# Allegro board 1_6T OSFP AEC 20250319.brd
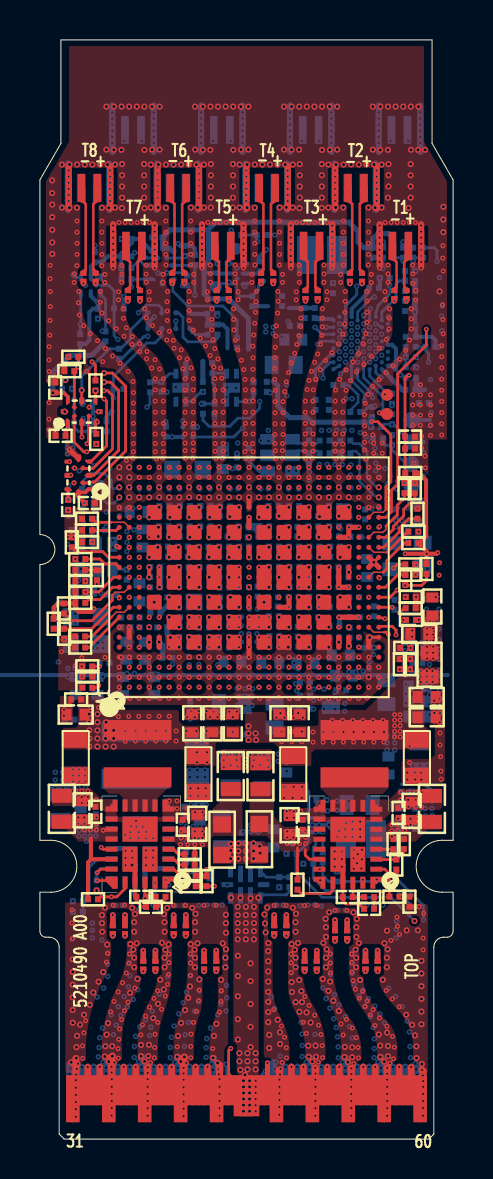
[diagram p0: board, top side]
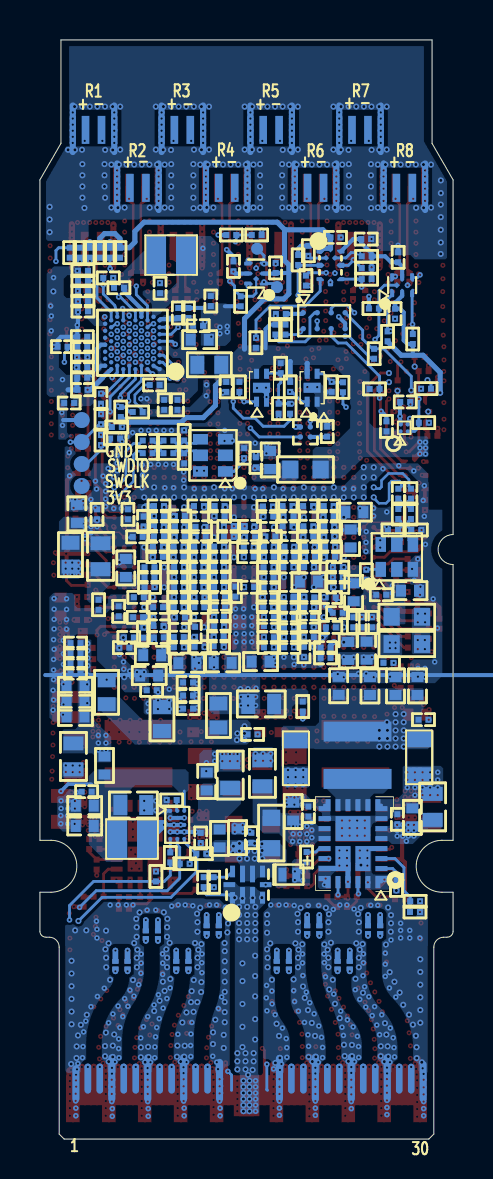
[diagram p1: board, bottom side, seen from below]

Outline 20.7 x 55 mm; copper layers: TOP, L2_GND, L3_GND, L4_SIG1, L5_GND, L6_PWR1, L7_PWR2, L8_GND, L9_SIG2, L10_GND, L11_GND, BOTTOM. Coordinates in mm from the lower left corner of the outline.
Outline path: 0,48 0,30.25 arc(0.75,29.5) 0,28.75 0,14.95 0.56,14.95 arc(1.86,13.65) 0.56,12.35 0,12.35 0,10.4 arc(0.09,10.19) 0.3,10.1 0.46,10.1 arc(0.82,9.95) 0.96,9.6 0.96,0.25 1.21,0 19.48,0 19.74,0.25 19.74,9.6 arc(19.88,9.95) 20.23,10.1 20.4,10.1 arc(20.61,10.19) 20.7,10.4 20.7,12.35 20.14,12.35 arc(18.84,13.65) 20.14,14.95 20.7,14.95 20.7,48 19.65,49.83 19.65,55 1.05,55 1.05,49.83 0,48

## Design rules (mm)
constraint set DEFAULT: min track width 0.14, pair gap 0.264
net group AVDDTXDRV_0P94: nets AVDDTXDRV_0P94 VDD_0P94
net group COMP1: nets COMP1 N17728804
net group DP1: nets LRXN1 LRXP1
net group DP2: nets LRXN2 LRXP2
net group DP3: nets LRXN3 LRXP3
net group DP4: nets LRXN4 LRXP4
net group DP5: nets LRXN5 LRXP5
net group DP6: nets LRXN6 LRXP6
net group DP7: nets LRXN7 LRXP7
net group DP8: nets LRXN8 LRXP8
net group DSP_PGOOD_M: nets DSP_PGOOD_M N17324668
net group EN1: nets EN1 N17689668
net group HRXN1: nets HRXN1 TXN1
net group HRXN2: nets HRXN2 TXN2
net group HRXN3: nets HRXN3 TXN3
net group HRXN4: nets HRXN4 TXN4
net group HRXN5: nets HRXN5 TXN5
net group HRXN6: nets HRXN6 TXN6
net group HRXN7: nets HRXN7 TXN7
net group HRXN8: nets HRXN8 TXN8
net group HRXP1: nets HRXP1 TXP1
net group HRXP2: nets HRXP2 TXP2
net group HRXP3: nets HRXP3 TXP3
net group HRXP4: nets HRXP4 TXP4
net group HRXP5: nets HRXP5 TXP5
net group HRXP6: nets HRXP6 TXP6
net group HRXP7: nets HRXP7 TXP7
net group HRXP8: nets HRXP8 TXP8
net group HTXN1: nets HTXN1 RXN1
net group HTXN2: nets HTXN2 RXN2
net group HTXN3: nets HTXN3 RXN3
net group HTXN4: nets HTXN4 RXN4
net group HTXN5: nets HTXN5 RXN5
net group HTXN6: nets HTXN6 RXN6
net group HTXN7: nets HTXN7 RXN7
net group HTXN8: nets HTXN8 RXN8
net group HTXP1: nets HTXP1 RXP1
net group HTXP2: nets HTXP2 RXP2
net group HTXP3: nets HTXP3 RXP3
net group HTXP4: nets HTXP4 RXP4
net group HTXP5: nets HTXP5 RXP5
net group HTXP6: nets HTXP6 RXP6
net group HTXP7: nets HTXP7 RXP7
net group HTXP8: nets HTXP8 RXP8
net group LTXN1: nets LTX_N1 LTXN1
net group LTXN2: nets LTX_N2 LTXN2
net group LTXN3: nets LTX_N3 LTXN3
net group LTXN4: nets LTX_N4 LTXN4
net group LTXN5: nets LTX_N5 LTXN5
net group LTXN6: nets LTX_N6 LTXN6
net group LTXN7: nets LTX_N7 LTXN7
net group LTXN8: nets LTX_N8 LTXN8
net group LTXP1: nets LTX_P1 LTXP1
net group LTXP2: nets LTX_P2 LTXP2
net group LTXP3: nets LTX_P3 LTXP3
net group LTXP4: nets LTX_P4 LTXP4
net group LTXP5: nets LTX_P5 LTXP5
net group LTXP6: nets LTX_P6 LTXP6
net group LTXP7: nets LTX_P7 LTXP7
net group LTXP8: nets LTX_P8 LTXP8
net group M_RSTN: nets M_RSTN NRST
net group MCU_SPI_CLK: nets MCU_SPI_CLK N17609315
net group MCU_SPI_CSB: nets MCU_SPI_CSB N17609312
net group MCU_SPI_MISO: nets MCU_SPI_MISO N17609318
net group MCU_SPI_MOSI: nets MCU_SPI_MOSI N17609321
net group N17421630: nets N16845549 N17421630
net group N17421668: nets N16845553 N17421668
net group N17495716: nets N17495710 N17495716
net group N17495757: nets N17495751 N17495757
net group N17738812: nets N17341552 N17738812
net group REFOUT0_CLK: nets DSP_REFCLK0_N DSP_REFCLK0_P
net group VCAP: nets VCAP VLXSMPS
net group 3V3_IN_DDM: nets 3V3_IN_DDM N17477873 VCC_OSFP
net group INT/RSTN: nets INT/RSTN M_INT OSFP_SCL SWDIO
net group LPWN/PRSN: nets LPWN/PRSN OSFP_SDA SWCLK
net group MISO_SLV_18: nets MISO_SLV_18 N17630589 N17630592
net group PHY_SELF_INIT_18: nets N17636718 N17636870 PHY_SELF_INIT_18
net group SE_50: nets EEPROM_MISO EEPROM_MOSI EEPROM_SCK
net group VDD_1P2: nets N17342760
net group VDD_3P3: nets VDD_3P3 VDD_3P3_ESD0 VDD_3P3_ESD1

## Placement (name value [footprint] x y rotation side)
C40  1uF  [0201C]  18.54 35.15 180 top
C42  0.1uF  [0201C]  14.48 36.74 90 bottom
C43  0.1uF  [0201C]  17.28 43.09 0 bottom
C45  0.1uF  [0201C]  8.63 41.29 0 bottom
C48  0.1uF  [0201C]  3.6 27.24 0 bottom
C49  22uF  [0402C]  2.16 27.44 180 bottom
C50  0.1uF_6.3V  [0201C]  2.75 32.29 90 bottom
C51  0.1uF_6.3V  [0201C]  2.11 32.29 90 bottom
C54  47uF  [0603C]  9.56 18.16 90 top
C56  22uF  [0402C]  8.65 20.81 90 top
C60  0.1uF/NC  [0201C]  19.57 39.65 180 bottom
C62  0.1uF  [0201C]  1.82 22 180 top
C67  0.47uF  [0201C]  7.16 15.73 90 top
C72  22uF  [0402C]  1.78 22.67 90 bottom
C78  8.2nF  [0201C]  5.56 11.62 180 top
C79  47uF  [0603C]  9.61 21.77 180 bottom
C81  22pF  [0201C]  5.08 12.12 180 top
C82  1uF  [0201C]  3.34 35.67 270 bottom
C83  1uF  [0201C]  2.4 36.88 0 bottom
C169  0.1uF  [0201C]  17.64 37.05 90 bottom
C170  0.1uF  [0201C]  18.58 38.1 180 bottom
C172  0.1uF  [0201C]  11.37 37.64 90 bottom
C173  0.1uF  [0201C]  13.77 41.34 270 bottom
C174  4.7uF  [0201C]  19.24 36.83 180 bottom
C199  0.1uF  [01005]  16.92 8.7 270 top
C200  0.1uF  [01005]  16.31 8.7 270 top
C201  0.1uF  [01005]  16.92 8.7 270 bottom
C202  0.1uF  [01005]  16.31 8.7 270 bottom
C203  0.1uF  [01005]  15.39 10.22 270 top
C204  0.1uF  [01005]  14.79 10.22 270 top
C205  0.1uF  [01005]  15.39 10.22 270 bottom
C206  0.1uF  [01005]  14.79 10.22 270 bottom
C207  0.1uF  [01005]  13.87 8.7 270 top
C208  0.1uF  [01005]  13.26 8.7 270 top
C209  0.1uF  [01005]  13.87 8.7 270 bottom
C210  0.1uF  [01005]  13.26 8.7 270 bottom
C211  0.1uF  [01005]  12.35 10.48 270 top
C212  0.1uF  [01005]  11.74 10.48 270 top
C213  0.1uF  [01005]  12.35 10.48 270 bottom
C214  0.1uF  [01005]  11.74 10.48 270 bottom
C215  0.1uF  [01005]  3.65 10.48 90 bottom
C216  0.1uF  [01005]  4.26 10.48 90 bottom
C217  0.1uF  [01005]  3.65 10.48 90 top
C218  0.1uF  [01005]  4.26 10.48 90 top
C219  0.1uF  [01005]  5.18 8.7 90 bottom
C220  0.1uF  [01005]  5.79 8.7 90 bottom
C221  0.1uF  [01005]  5.18 8.7 90 top
C222  0.1uF  [01005]  5.79 8.7 90 top
C223  0.1uF  [01005]  6.7 10.48 90 bottom
C224  0.1uF  [01005]  7.31 10.48 90 bottom
C225  0.1uF  [01005]  6.7 10.48 90 top
C226  0.1uF  [01005]  7.31 10.48 90 top
C227  0.1uF  [01005]  8.23 8.7 90 bottom
C228  0.1uF  [01005]  8.83 8.7 90 bottom
C229  0.1uF  [01005]  8.23 8.7 90 top
C230  0.1uF  [01005]  8.83 8.7 90 top
C266  22uF  [0402C]  7.63 20.81 90 top
C338  10uF  [0402C]  10.79 15.08 90 bottom
C342  22uF  [0402C]  12.69 40 180 bottom
C346  47uF  [0603C]  17.66 29.16 270 bottom
C417  0.1uF  [0201C]  10.11 15.08 90 bottom
C419  1uF  [0201C]  12.77 40.7 0 bottom
C420  0.1uF  [0201C]  5.89 45.12 180 bottom
C421  0.1uF  [0201C]  4.36 45.04 180 bottom
C424  0.1uF  [0201C]  2.91 41.3 270 bottom
C425  0.1uF  [0201C]  2.75 44.13 270 bottom
C426  0.1uF  [0201C]  1.04 35.19 180 top
C427  0.1uF  [0201C]  0.77 37.61 90 top
C428  22uF  [0402C]  7.89 15.78 90 top
C431  10uF  [0402C]  5.13 30.05 90 bottom
C437  22uF  [0402C]  1.79 21.24 180 top
C441  22uF  [0402C]  9.66 20.81 90 top
C444  22uF  [0402C]  2.88 22.67 90 bottom
C445  22uF  [0402C]  4.16 22.67 90 bottom
C447  22uF  [0402C]  5.73 22.68 90 bottom
C454  1uF  [0201C]  6.16 29.65 0 bottom
C455  0.1uF  [0201C]  18.58 39.14 180 bottom
C456  100uF  [0805C]  1.79 19.08 270 top
C458  22uF  [0402C]  8.01 16.39 90 bottom
C459  22uF  [0402C]  2.04 16.1 90 bottom
C460  0.47uF  [0201C]  2.79 16 90 bottom
C461  0.47uF  [0201C]  7.25 16.39 90 bottom
C466  100uF  [0805C]  1.7 19.11 270 bottom
C467  22uF  [0402C]  2.14 16.45 90 top
C468  0.47uF  [0201C]  2.78 16.38 90 top
C469  47uF  [0603C]  1.02 16.62 90 bottom
C475  0.1uF  [0201C]  18.54 41.43 180 bottom
C476  0.1uF  [0201C]  13.81 36.74 90 bottom
C477  220pF  [0201C]  16.74 42.6 180 bottom
C478  4.7uF  [0201C]  12.14 41.93 90 bottom
C479  0.1uF  [0201C]  18.56 37.49 180 bottom
C480  0.1uF  [0201C]  14.68 42.58 270 bottom
C481  1uF  [0201C]  18.54 41.94 180 bottom
C485  47uF  [0603C]  11.05 18.15 90 top
C492  8.2nF  [0201C]  16.49 11.52 180 top
C493  0.1uF  [0201C]  10.04 20.25 180 bottom
C494  22uF  [0402C]  13.02 20.81 90 top
C497  22uF  [0402C]  12.51 15.71 90 top
C498  22uF  [0402C]  18.62 16.42 90 top
C499  0.47uF  [0201C]  17.97 16.32 90 top
C500  0.47uF  [0201C]  13.17 15.73 90 top
C501  22pF  [0201C]  15.43 12.11 180 top
C502  22uF  [0402C]  19.38 22.12 0 top
C503  22uF  [0402C]  19.38 21.11 0 top
C504  22uF  [0402C]  12 20.81 90 top
C508  100uF  [0805C]  12.69 18.27 270 top
C566  22uF  [0402C]  9.64 23.89 180 bottom
C642  22uF  [0402C]  18.45 15.67 0 bottom
C643  22uF  [0402C]  18.45 16.68 0 bottom
C644  47uF  [0603C]  16.02 16.71 180 bottom
C645  0.1uF  [0201C]  18.36 17.38 0 bottom
C646  22uF  [0402C]  12.34 17.89 90 bottom
C648  0.47uF  [0201C]  12.64 15.07 270 bottom
C649  0.1uF  [0201C]  9.88 33.86 90 bottom
C650  0.1uF_6.3V  [0201C]  15.3 34.95 0 bottom
C651  0.1uF_6.3V  [0201C]  15.3 34.32 0 bottom
C652  22uF  [0402C]  9.17 33.98 90 bottom
C653  0.1uF  [0201C]  4.53 25.86 90 bottom
C654  10uF  [0402C]  5.26 24.43 270 bottom
C655  47uF  [0603C]  1.1 16.52 90 top
C656  47uF  [0603C]  9.55 18.3 90 bottom
C657  47uF  [0603C]  19.64 16.52 90 top
C658  100uF  [0805C]  7.88 19.06 270 bottom
C659  100uF  [0805C]  7.94 18.27 270 top
C661  100uF  [0805C]  18.88 19.08 270 top
C664  10uF  [0402C]  7.23 27.89 0 bottom
C665  0.1uF  [0201C]  11.72 28.63 180 bottom
C744  0.1uF  [0201C]  13.73 28.63 180 bottom
C745  0.1uF  [0201C]  12.72 29.14 180 bottom
C746  0.1uF  [0201C]  11.72 27.63 180 bottom
C747  0.1uF  [0201C]  11.72 29.65 0 bottom
C748  0.1uF  [0201C]  14.79 29.14 180 bottom
C749  0.1uF  [0201C]  14.79 29.65 180 bottom
C750  0.1uF  [0201C]  12.72 29.65 180 bottom
C751  0.1uF  [0201C]  13.75 29.14 0 bottom
C752  0.1uF  [0201C]  13.75 29.65 0 bottom
C753  0.1uF  [0201C]  11.72 28.13 180 bottom
C754  0.1uF  [0201C]  13.73 28.12 180 bottom
C755  0.1uF  [0201C]  11.72 29.14 0 bottom
C756  0.1uF  [0201C]  10.24 29.14 0 bottom
C757  0.1uF  [0201C]  9.23 29.14 180 bottom
C758  0.1uF  [0201C]  8.2 29.64 0 bottom
C759  0.1uF  [0201C]  9.24 28.1 0 bottom
C760  0.1uF  [0201C]  7.17 29.65 180 bottom
C761  0.1uF  [0201C]  7.17 29.14 180 bottom
C762  0.1uF  [0201C]  9.24 27.6 0 bottom
C763  0.1uF  [0201C]  9.23 29.65 180 bottom
C764  0.1uF  [0201C]  8.2 29.14 0 bottom
C765  0.1uF  [0201C]  10.24 29.65 0 bottom
C766  0.1uF  [0201C]  9.24 28.61 0 bottom
C767  1uF  [0201C]  8.25 28.62 180 bottom
C778  22uF  [0402C]  11.54 23.83 0 bottom
C779  2.2uF  [0201C]  9.26 26.64 180 bottom
C780  2.2uF  [0201C]  11.67 26.65 0 bottom
C781  10uF  [0402C]  18.85 31.28 90 bottom
C782  10uF  [0402C]  4.95 31.37 180 bottom
C783  2.2uF  [0201C]  16.29 31.26 90 bottom
C784  2.2uF  [0201C]  17.84 31.26 90 bottom
C785  1uF  [0201C]  6.39 24.08 0 bottom
C786  1uF  [0201C]  6.39 24.58 0 bottom
C787  1uF  [0201C]  15.51 30.91 270 bottom
C788  1uF  [0201C]  15.8 30.13 180 bottom
C789  1uF  [0201C]  13.28 21.54 180 bottom
C790  1uF  [0201C]  15.1 22.46 0 bottom
C791  10uF  [0402C]  15.23 23.19 0 bottom
C792  10uF  [0402C]  13.31 23.81 180 bottom
C793  2.2uF  [0201C]  13.28 22.19 180 bottom
C794  2.2uF  [0201C]  13.28 22.85 180 bottom
C795  10uF  [0402C]  18.92 21.15 0 bottom
C796  10uF  [0402C]  18.92 22.65 0 bottom
C797  1uF  [0201C]  18.92 24.31 0 bottom
C798  1uF  [0201C]  18.92 24.82 0 bottom
C799  10uF  [0402C]  19.66 26.65 90 top
C801  1uF  [0201C]  7.23 25.11 180 bottom
C802  1uF  [0201C]  7.47 24.38 270 bottom
C803  10uF  [0402C]  19 25.28 180 top
C805  1uF  [0201C]  14.76 25.68 0 bottom
C806  1uF  [0201C]  13.68 26.1 180 bottom
C807  10uF  [0402C]  4.98 27.36 270 bottom
C808  10uF  [0402C]  16.39 28.58 90 bottom
C809  1uF  [0201C]  15.21 27.61 180 bottom
C810  1uF  [0201C]  5.77 28.62 0 bottom
C811  10uF  [0402C]  4.33 24.44 270 bottom
C812  10uF  [0402C]  15.07 24.21 180 bottom
C813  1uF  [0201C]  16.24 25.1 0 bottom
C814  1uF  [0201C]  3.24 23.83 180 bottom
C815  2.2uF  [0201C]  5.78 26.34 0 bottom
C816  2.2uF  [0201C]  16.75 26.41 90 bottom
C817  0.1uF  [0201C]  15.74 27.11 0 bottom
C818  0.1uF  [0201C]  14.78 26.61 180 bottom
C819  0.1uF  [0201C]  14.74 25.1 180 bottom
C820  0.1uF  [0201C]  9.27 27.11 180 bottom
C821  0.1uF  [0201C]  6.23 31.17 0 bottom
C822  0.1uF  [0201C]  9.28 31.65 180 bottom
C823  0.1uF  [0201C]  9.26 31.16 180 bottom
C824  0.1uF  [0201C]  14.73 31.17 180 bottom
C825  0.1uF  [0201C]  6.23 31.68 0 bottom
C826  0.1uF  [0201C]  11.7 31.68 0 bottom
C827  0.1uF  [0201C]  14.73 31.68 180 bottom
C828  0.1uF  [0201C]  11.7 31.17 0 bottom
C829  0.1uF  [0201C]  8.25 31.17 0 bottom
C830  0.1uF  [0201C]  11.23 30.15 0 bottom
C831  0.1uF  [0201C]  11.23 30.66 0 bottom
C832  0.1uF  [0201C]  13.69 31.18 0 bottom
C833  0.1uF  [0201C]  12.73 31.68 180 bottom
C834  0.1uF  [0201C]  7.26 31.68 180 bottom
C835  0.1uF  [0201C]  10.2 30.66 180 bottom
C836  0.1uF  [0201C]  8.3 31.68 0 bottom
C837  0.1uF  [0201C]  14.74 30.16 0 bottom
C838  0.1uF  [0201C]  7.2 27.11 180 bottom
C839  0.1uF  [0201C]  13.74 27.12 0 bottom
C840  0.1uF  [0201C]  8.24 26.61 0 bottom
C841  0.1uF  [0201C]  12.71 26.61 180 bottom
C842  0.1uF  [0201C]  12.71 27.11 180 bottom
C843  0.1uF  [0201C]  13.69 30.66 180 bottom
C844  0.1uF  [0201C]  13.69 30.15 180 bottom
C845  2.2uF  [0201C]  18.92 23.81 0 bottom
C846  2.2uF  [0201C]  18.92 23.31 0 bottom
C847  0.1uF  [0201C]  13.74 25.12 0 bottom
C848  0.1uF  [0201C]  8.22 24.61 0 bottom
C849  0.1uF  [0201C]  9.23 25.11 180 bottom
C850  0.1uF  [0201C]  13.74 24.62 0 bottom
C851  0.1uF  [0201C]  8.29 30.66 180 bottom
C852  0.1uF  [0201C]  12.65 30.15 0 bottom
C853  0.1uF  [0201C]  12.66 30.64 0 bottom
C854  0.1uF  [0201C]  11.72 26.17 180 bottom
C855  0.1uF  [0201C]  11.72 25.67 180 bottom
C856  0.1uF  [0201C]  9.16 30.15 0 bottom
C857  0.1uF  [0201C]  15.21 28.61 180 bottom
C858  0.1uF  [0201C]  5.77 28.12 0 bottom
C859  0.1uF  [0201C]  5.77 27.61 0 bottom
C860  0.1uF  [0201C]  15.21 28.11 180 bottom
C861  0.1uF  [0201C]  16.47 24.59 0 bottom
C862  0.1uF  [0201C]  4.06 25.86 90 bottom
C863  0.1uF  [0201C]  6.12 25.61 0 bottom
C864  0.1uF  [0201C]  15.78 26.11 180 bottom
C865  0.1uF  [0201C]  11.68 27.11 0 bottom
C866  0.1uF  [0201C]  6.13 27.11 0 bottom
C871  0.1uF  [0201C]  6.21 30.66 180 bottom
C872  0.1uF  [0201C]  6.21 30.15 180 bottom
C873  0.1uF  [0201C]  14.74 30.66 0 bottom
C874  0.1uF  [0201C]  7.2 26.61 180 bottom
C875  0.1uF  [0201C]  13.75 26.62 0 bottom
C876  0.1uF  [0201C]  8.24 27.11 0 bottom
C877  0.1uF  [0201C]  7.25 30.66 0 bottom
C878  0.1uF  [0201C]  7.25 30.15 0 bottom
C880  0.1uF  [0201C]  1.48 20.98 180 bottom
C881  0.1uF  [0201C]  11.74 24.67 0 bottom
C882  0.1uF  [0201C]  11.74 25.17 0 bottom
C883  0.1uF  [0201C]  9.23 24.6 180 bottom
C884  0.1uF  [0201C]  12.93 25.38 90 bottom
C885  0.1uF  [0201C]  9.23 26.1 0 bottom
C886  0.1uF  [0201C]  9.23 25.67 0 bottom
C887  0.1uF  [0201C]  7.23 25.66 0 bottom
C888  0.1uF  [0201C]  8.22 25.6 180 bottom
C889  0.1uF  [0201C]  8.22 26.07 180 bottom
C890  0.1uF  [0201C]  7.27 26.11 0 bottom
C891  0.1uF  [0201C]  13.27 41.34 270 bottom
C892  0.1uF  [0201C]  14.95 37.74 180 bottom
C898  22uF  [0402C]  18.92 21.9 0 bottom
C899  47uF  [0603C]  19.02 19.15 270 bottom
C909  0.1uF  [0201C]  8.89 43.59 90 bottom
C910  0.1uF  [0201C]  11 43.67 270 bottom
C914  0.1uF  [0201C]  2.5 31.83 0 top
C915  0.1uF  [0201C]  1.41 31.73 270 top
C916  0.1uF  [01005]  18.36 42.26 90 top
C917  0.1uF  [01005]  17.76 42.26 90 top
C918  0.1uF  [01005]  16.14 43.12 90 top
C919  0.1uF  [01005]  15.53 43.12 90 top
C920  0.1uF  [01005]  13.91 42.26 90 top
C921  0.1uF  [01005]  13.31 42.26 90 top
C922  0.1uF  [01005]  11.69 43.12 90 top
C923  0.1uF  [01005]  11.08 43.12 90 top
C924  0.1uF  [01005]  9.46 42.26 90 top
C925  0.1uF  [01005]  8.85 42.26 90 top
C926  0.1uF  [01005]  7.24 43.12 90 top
C927  0.1uF  [01005]  6.63 43.12 90 top
C928  0.1uF  [01005]  5.01 42.26 90 top
C929  0.1uF  [01005]  4.41 42.26 90 top
C930  0.1uF  [01005]  2.79 43.12 90 top
C931  0.1uF  [01005]  2.18 43.12 90 top
C932  0.1uF  [0201C]  6.31 35.4 270 bottom
C933  0.1uF  [0201C]  18.58 40.14 180 bottom
C934  0.1uF  [0201C]  6.16 29.14 0 bottom
C935  0.1uF  [0201C]  7.21 28.62 0 bottom
C936  1uF  [0201C]  8.22 25.09 0 bottom
C937  1uF  [0201C]  12.7 24.63 180 bottom
C938  1uF  [0201C]  10.91 27.4 90 bottom
C939  1uF  [0201C]  12.5 12.85 270 bottom
C940  0.1uF  [0201C]  10.17 30.11 180 bottom
C941  1uF  [0201C]  10.22 27.62 180 bottom
C942  2.2uF  [0201C]  13.73 27.62 180 bottom
C943  2.2uF  [0201C]  12.76 27.63 0 bottom
C944  2.2uF  [0201C]  12.76 28.13 0 bottom
C945  2.2uF  [0201C]  12.76 28.63 0 bottom
D1  BZT52C3V9LP-7  [X1-DFN1006-2]  8.2 13.23 180 bottom
J1  OSFP Connector  [OSFP_1600G_FINGER]  19.2 2.16 270 top
J2  4 Pin SMD  [4_PIN_SMD_OSFP]  18.06 44.7 180 top
J3  4 Pin SMD  [4_PIN_SMD_OSFP]  9.16 44.7 180 top
J4  4 Pin SMD  [4_PIN_SMD_OSFP]  18.01 50.5 180 bottom
J5  4 Pin SMD  [4_PIN_SMD_OSFP]  9.11 50.5 180 bottom
J6  4 Pin SMD  [4_PIN_SMD_OSFP]  15.84 47.6 180 top
J7  4 Pin SMD  [4_PIN_SMD_OSFP]  6.93 47.6 180 top
J8  4 Pin SMD  [4_PIN_SMD_OSFP]  15.79 47.6 180 bottom
J9  4 Pin SMD  [4_PIN_SMD_OSFP]  6.89 47.6 180 bottom
J10  4 Pin SMD  [4_PIN_SMD_OSFP]  13.61 44.7 180 top
J11  4 Pin SMD  [4_PIN_SMD_OSFP]  4.71 44.7 180 top
J12  4 Pin SMD  [4_PIN_SMD_OSFP]  13.56 50.5 180 bottom
J13  4 Pin SMD  [4_PIN_SMD_OSFP]  4.66 50.5 180 bottom
J14  4 Pin SMD  [4_PIN_SMD_OSFP]  11.39 47.6 180 top
J15  4 Pin SMD  [4_PIN_SMD_OSFP]  2.49 47.6 180 top
J16  4 Pin SMD  [4_PIN_SMD_OSFP]  11.34 47.6 180 bottom
J17  4 Pin SMD  [4_PIN_SMD_OSFP]  2.44 47.6 180 bottom
J18  SWD  [HDR_1X4_50MIL_WIRE_P1R1]  18.61 34.88 0 bottom
L4  110nH  [L110NH_XGL4020_4X4X2R1]  4.89 19.28 90 top
L9  BLE18PS080SN1D  [0603R]  11.76 21.2 270 bottom
L14  WFCP04024L000FE66  [0402R]  17.46 18.69 270 bottom
L19  BLE18PS080SN1D  [0603R]  19.17 29.24 270 bottom
L27  DFE21CCN2R2MEL_2.2uH  [2016L]  14.13 44.24 180 bottom
L30  BLE18PK160SN1D  [0603R]  14.58 21.02 270 bottom
L81  BLE18PS080SN1D  [0603R]  12.21 38.74 180 bottom
L82  BLM18SN220TH1D  [0603L]  2.32 24.77 0 bottom
L84  LQM18PN4R7MFRL  [0603L]  2.32 26.13 180 bottom
L85  BLM18SN220TH1D  [0603L]  9.13 14.98 90 top
L86  BLM18SN220TH1D  [0603L]  10.99 15 90 top
L87  110nH  [L110NH_XGL4020_4X4X2R1]  4.79 19.21 90 bottom
L88  110nH  [L110NH_XGL4020_4X4X2R1]  15.76 19.28 90 top
L89  SRP2012TMA-R22M  [2016L]  16.08 15.01 0 bottom
L91  BLM18SN220TH1D  [0603L]  9.1 15.31 90 bottom
L93  BLM15KD200SN1D  [0402R]  11.7 15.05 90 bottom
L95  LQM18PN4R7MFRL  [0603L]  7.4 33.5 180 bottom
L96  FBMJ1608HS280NTR  [0603R]  19.52 23.73 90 top
L98  BLM18BD121SN1D  [0603R]  17.36 22.36 90 bottom
NOREF  -  []  -64.29 38.56 0 top
NOREF#2  -  []  -115.78 -190.55 0 top
NOREF#3  -  []  282.89 140.91 0 top
R3  0R  [0201R]  8.74 36.55 90 bottom
R4  10K/NC  [0201R]  16.85 35.63 0 bottom
R5  0R  [0201R]  5.52 37.62 270 bottom
R6  10K/NC  [0201R]  16.93 35.06 0 bottom
R10  0R  [0201R]  1.36 37.55 180 bottom
R11  0R  [0201R]  2.78 37.71 270 top
R12  0R  [0201R]  3.96 39.3 90 bottom
R13  10K/NC  [0201R]  16.65 36.38 90 bottom
R15  0R  [0201R]  1.68 39.14 0 top
R22  NTCG063JF103FTB  [0201R]  18.55 33.33 180 top
R23  10K  [0201R]  17.7 44.35 90 bottom
R24  10K  [0201R]  18.2 44.35 90 bottom
R25  4.99K  [0201R]  18.54 34.55 0 top
R28  10K  [0201R]  10.71 37.64 270 bottom
R29  10K  [0201R]  8.16 37.64 270 bottom
R30  3K3  [0201R]  2.82 35.04 270 top
R31  8.06K  [0201R]  8.17 36.55 270 bottom
R32  3K3  [0201R]  8.9 40.51 90 bottom
R35  150R/NC  [0201R]  3.01 30.48 0 bottom
R36  150R/NC  [0201R]  1.84 30.48 180 bottom
R40  2K  [0201R]  8.4 40.51 90 bottom
R41  100K  [0201R]  1.47 38.43 180 top
R44  10K  [0201R]  4.35 28.24 270 bottom
R46  6K2  [0201R]  7.56 13.18 180 top
R62  2K  [0201R]  12.61 14.28 0 bottom
R63  10K  [0201R]  15.8 36.38 0 bottom
R64  2K  [0201R]  13.45 13.77 0 bottom
R73  5K1  [0201R]  3.97 41.56 0 bottom
R75  1K/NC  [0201R]  0.69 25.79 90 top
R79  10K  [0201R]  10.47 34.32 90 bottom
R105  8.45K  [0201R]  9.84 45.24 180 bottom
R233  5K1/NC  [0201R]  9.88 39.84 270 bottom
R404  10K/NC  [0201R]  2.85 28.21 270 top
R411  10K  [0201R]  11.11 45.24 0 bottom
R579  2K  [0201R]  3.28 40.17 90 bottom
R580  2K  [0201R]  2.02 40.03 90 bottom
R581  10K  [0201R]  7.26 44.45 90 bottom
R582  10K  [0201R]  7.76 43.99 90 bottom
R583  10K  [0201R]  4.33 43.03 0 bottom
R599  0R/NC  [0201R]  18.58 39.64 0 bottom
R600  10K  [0201R]  19.21 44.35 90 bottom
R601  10K  [0201R]  18.7 44.35 90 bottom
R602  10K  [0201R]  1.47 35.85 180 bottom
R603  10K  [0201R]  18.58 38.63 180 bottom
R607  22K  [0201R]  7.56 12.65 180 top
R608  1K  [0201R]  6.05 12.12 0 top
R610  6K2  [0201R]  1.91 11.36 0 bottom
R618  47K  [0201R]  7.5 14.25 180 top
R620  10K  [0201R]  2.66 12 0 top
R621  10K  [0201R]  12.9 12.73 270 top
R622  15K  [0201R]  16.69 44.35 270 bottom
R623  10K/NC  [0201R]  17.19 44.35 270 bottom
R629  47K/NC  [0201R]  7.5 13.72 180 top
R635  100K  [0201R]  8.35 12.9 90 top
R640  0R  [0201R]  18.54 42.44 180 bottom
R647  0R  [0201R]  17.64 36.02 90 bottom
R648  0R  [0201R]  17.64 34.98 90 bottom
R649  50R  [0201R]  7.53 21.64 270 bottom
R650  50R  [0201R]  17.76 26.73 270 bottom
R657  4.99K  [0201R]  8.63 38.58 270 bottom
R685  47K  [0201R]  7.34 14.11 270 bottom
R690  2K  [0201R]  18.59 25.98 0 top
R691  2K  [0201R]  1.2 26.55 90 top
R693  2K  [0201R]  18.71 29.82 0 top
R694  2K  [0201R]  2.02 26.83 180 top
R710  22K  [0201R]  17.76 12.13 180 top
R711  6K2  [0201R]  17.86 13.74 90 top
R712  1K  [0201R]  16.49 12.11 0 top
R715  100K  [0201R]  18.51 11.88 270 top
R718  13K  [0201R]  2.37 22.58 180 top
R719  13K  [0201R]  18.57 26.56 0 top
R735  0R  [0201R]  12 12.85 90 bottom
R748  0R  [0201R]  17.72 14.76 270 top
R755  10K  [0201R]  1.6 29.86 90 top
R756  205K  [0201R]  14.1 16.97 0 bottom
R758  0R  [0201R]  18.31 27.99 270 top
R759  150R/NC  [0201R]  13.47 35.21 90 bottom
R760  150R/NC  [0201R]  13.47 34.07 270 bottom
R761  0R  [0201R]  18.54 23.77 270 top
R762  0R  [0201R]  18.31 24.58 0 top
R764  1K  [0201R]  2.02 25.15 180 top
R765  1K  [0201R]  18.03 23.77 90 top
R766  1K  [0201R]  2.02 24.6 180 top
R767  1K  [0201R]  1.21 25.29 270 top
R769  10K  [0201R]  2.02 28.48 0 top
R770  1K  [0201R]  2.37 23.65 180 top
R771  1K/NC  [0201R]  2.37 23.14 180 top
R778  47K/NC  [0201R]  1.9 11.9 0 bottom
R779  47K/NC  [0201R]  18.23 14.76 270 top
R780  10R  [0201R]  5 25.86 90 bottom
R781  10R  [0201R]  15.52 25.34 90 bottom
R783  0R/NC  [0201R]  18.56 28.24 180 top
R787  0R  [0201R]  14.26 34.32 180 bottom
R788  0R  [0201R]  14.26 34.95 180 bottom
R789  0R  [0201R]  2.75 31.28 270 bottom
R790  0R  [0201R]  2.11 31.28 270 bottom
R815  0R  [0201R]  18.27 32.57 90 top
R818  2K  [0201R]  2.02 27.38 0 top
R819  2K  [0201R]  2.02 27.93 0 top
R829  0R  [0201R]  2.02 29.03 180 top
R830  0R  [0201R]  18.55 28.76 0 top
R833  0R  [0201R]  18.71 30.4 0 top
R834  0R  [0201R]  18.92 31.29 90 top
R835  0R  [0201R]  2.36 30.46 180 top
R836  0R  [0201R]  2.36 29.88 180 top
R837  0R  [0201R]  18.78 32.57 90 top
R838  0R  [0201R]  2.36 31.04 180 top
R839  0R  [0201R]  18.58 27.13 0 top
R840  5K1  [0201R]  10.64 41.92 270 bottom
R841  4.99K  [0201R]  18.54 42.94 0 bottom
R842  4.99K  [0201R]  18.54 43.45 0 bottom
R843  10K  [0201R]  6.08 37.64 270 bottom
R845  0R  [0201R]  2.84 12.7 90 bottom
R849  10K  [0201R]  7.37 42.96 270 bottom
R850  100K  [0201R]  14.89 13.14 90 bottom
R852  22K  [0201R]  14.17 14.09 90 bottom
R854  10K  [0201R]  19.37 28.53 90 top
R855  10K/NC  [0201R]  4.33 43.59 0 bottom
R856  10K/NC  [0201R]  4.33 44.17 0 bottom
R857  3K3/NC  [0201R]  3.93 37.54 0 bottom
TP1  TP 1x1  [TP80]  8.82 42.64 180 bottom
TP2  TP 1x1  [TP80]  9.82 44.55 180 bottom
TP3  TP 1x1  [TP80]  17.39 37.24 0 top
TP4  TP 1x1  [TP80]  17.39 36.29 0 top
U1  Leo A0 621p 12x14  [DSP_1600G_12MMX14MM]  10.48 28.11 90 top
U2  STM32H563MIY3QTR  [WLCSP80]  16.07 39.85 0 bottom
U4  MIC842HYMT-T5  [TDFN_MIC842]  9.6 37.6 180 bottom
U8  NCP148AFCT180T2G  [WLCSP4]  2.45 35.59 90 bottom
U10  TCA9416DTMR  [X2SON8]  2.55 42.73 90 bottom
U17  TXU0304DTR  [X2SON12]  2.09 36.4 90 top
U20  TPS62876QWRZVRQ1  [VQFN]  5.02 14.75 180 top
U21  TPS62876QWRZVRQ1  [VQFN]  5.02 14.79 0 bottom
U22  M95P32-EXCST/EF  [M95P32_WLCSP8]  6.46 40.95 90 bottom
U24  MIC842HYMT-T5  [TDFN_MIC842]  7.06 37.6 180 bottom
U26  TPS62876QWRZVRQ1  [VQFN]  15.43 14.75 180 top
U32  TPS22998RYZR  [WQFN-10]  10.3 12.73 90 bottom
U37  TPS628660BYCGR  [TPS62864_DSBGA]  13.82 15.72 180 bottom
U38  TXU0304DTR  [X2SON12]  6.14 43.72 180 bottom
U46  TXU0304DTR  [X2SON12]  1.93 33.21 180 top
U47  SN74LVC1G14YZVR  [BGA4N50P2X2_88X88X50N]  7.4 35.38 270 bottom
U48  TCA9416DTMR  [X2SON8]  9.87 43.31 0 bottom
UNK647  47uF  [0603C]  11.17 18.21 90 bottom
Y1  SiT9501AE-01P1-3310-156.250000E  [SG2016EGN]  2.82 29.13 180 bottom
Y2  SiT9501AE-01P1-3310-156.250000E  [SG2016EGN]  12.03 34.21 90 bottom

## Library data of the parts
C40 C42 C43 C45 C60 C82 C83 C169 C170 C172 C174 C199-C230 C419-C421 C424-C427 C455 C475-C481 C649 C891 C892 C909 C910 C914-C933 C939 = CAP NP
C48 C50 C51 C650 C651 = CAP NP: signal model: CAP_NP_0201_0.1UF_6.3V_0.1uF_6.3V
C49 C62 C67 C78 C173 C342 C431 C454 C460 C461 C468 C492 C493 C499-C501 C566 C645 C648 C652 C664 C665 C744-C767 C778-C799 C801-C803 C805-C866 C871-C878 C880-C890 C898 C934-C938 C940-C945 = C0402
C54 C56 C72 C79 C266 C338 C346 C417 C428 C437 C441 C444 C445 C447 C456 C458 C459 C466 C467 C469 C485 C494 C497 C498 C502-C504 C508 C642-C644 C646 C653-C659 C661 C899 UNK647 = C
C81 = C0402: signal model: CAP_NP_0201_0.1UF_6.3V_0.1uF_6.3V
D1 = DIODE
J1 = OSFP connector_0
J2-J17 = 4-Pin-Pad-SMD_0
J18 = Solder Pad
L4 L14 L27 L82 L85-L89 L91 L93 = INDUCTOR
L9 L19 L30 L81 L96 L98 = INDUCTOR: User Part Number: pn
L84 L95 = INDUCTOR_0
R3-R6 R10-R13 R15 R23-R25 R28-R32 R35 R36 R40 R41 R44 R46 R62-R64 R73 R75 R79 R105 R233 R404 R411 R579-R583 R599-R603 R607 R608 R610 R618 R620-R623 R629 R635 R640 R647-R650 R657 R685 R690 R691 R693 R694 R710-R712 R715 R718 R719 R735 R748 R755 R756 R758-R762 R764-R767 R769-R771 R778-R781 R783 R815 R818 R819 R829 R830 R833-R843 R845 R849 R850 R852 R854-R857 = R
R22 = R-0000-1p-0201_1
R787-R790 = R: signal model: R_0201_0_0
TP1-TP4 = TP 1x1
U1 = Leo A0 621p 12x14
U2 = STM32H563MIY3QTR
U4 U24 = MIC842HYMT-T5
U8 = NCP148AFCT180T2G
U10 U48 = TCA9416DTMR
U17 U38 U46 = TXU0304DTR
U20 U21 U26 = TPS62876QWRZVRQ1
U22 = M95P32-IXCST/EF
U32 = TPS22998RYZR
U37 = tps62866
U47 = SN74LVC1G14YZVR
Y1 Y2 = SG2520VHN 156.2500M-ECHPZA

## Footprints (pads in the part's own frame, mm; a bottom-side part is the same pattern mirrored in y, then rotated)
4_PIN_SMD_OSFP
  rect 0.3x1.4 smd: 1(-1.04,0) 4(1.04,0)
  rect 0.38x1.4 smd: 2(-0.4,0) 3(0.4,0)
0201C
  rect 0.3x0.3 smd: 1(-0.25,0) 2(0.25,0)
0201R
  rect 0.3x0.3 smd: 1(-0.25,0) 2(0.25,0)
0402C
  rect 0.5x0.599 smd: 1(-0.45,0) 2(0.45,0)
0402R
  rect 0.5x0.599 smd: 1(-0.45,0) 2(0.45,0)
0603C
  rect 0.7x1 smd: 1(-0.65,0) 2(0.65,0)
0603L
  rect 0.813x0.889 smd: 1(-0.762,0) 2(0.762,0)
0603R
  rect 0.7x0.9 smd: 1(-0.6,0) 2(0.6,0)
0805C
  rect 0.8x1.2 smd: 1(-0.9,0) 2(0.9,0)
01005
  rect 0.231x0.3 smd: 1(-0.192,0) 2(0.192,0)
2016L
  rect 1x1.9 smd: 1(-0.75,0) 2(0.75,0)
BGA4N50P2X2_88X88X50N
  round 0.27 smd: A1(-0.25,0.25) A2(0.25,0.25) B1(-0.25,-0.25) B2(0.25,-0.25)
DSP_1600G_12MMX14MM
  round 0.254 smd: A1(-5.5,6.5) A2(-5,6.5) A3(-4.5,6.5) A4(-4,6.5) A5(-3.5,6.5) A6(-3,6.5) A7(-2.5,6.5) A12(0,6.5) A13(0.5,6.5) A14(1,6.5) A15(1.5,6.5) A16(2,6.5) A19(3.5,6.5) A20(4,6.5) A21(4.5,6.5) A22(5,6.5) A23(5.5,6.5) AA1(-5.5,-3.5) AA2(-5,-3.5) AA3(-4.5,-3.5) AA4(-4,-3.5) AA5(-3.5,-3.5) AA6(-3,-3.5) AA7(-2.5,-3.5) AA8(-2,-3.5) AA9(-1.5,-3.5) AA10(-1,-3.5) AA11(-0.5,-3.5) AA12(0,-3.5) AA13(0.5,-3.5) AA14(1,-3.5) AA15(1.5,-3.5) AA16(2,-3.5) AA17(2.5,-3.5) AA18(3,-3.5) AA19(3.5,-3.5) AA20(4,-3.5) AA21(4.5,-3.5) AA22(5,-3.5) AA23(5.5,-3.5) AB1(-5.5,-4) AB2(-5,-4) AB3(-4.5,-4) AB4(-4,-4) AB5(-3.5,-4) AB6(-3,-4) AB7(-2.5,-4) AB8(-2,-4) AB9(-1.5,-4) AB10(-1,-4) AB11(-0.5,-4) AB12(0,-4) AB13(0.5,-4) AB14(1,-4) AB15(1.5,-4) AB16(2,-4) AB17(2.5,-4) AB18(3,-4) AB19(3.5,-4) AB20(4,-4) AB21(4.5,-4) AB22(5,-4) AB23(5.5,-4) AC1(-5.5,-4.5) AC2(-5,-4.5) AC3(-4.5,-4.5) AC4(-4,-4.5) AC5(-3.5,-4.5) AC6(-3,-4.5) AC7(-2.5,-4.5) AC8(-2,-4.5) AC9(-1.5,-4.5) AC10(-1,-4.5) AC11(-0.5,-4.5) AC12(0,-4.5) AC13(0.5,-4.5) AC14(1,-4.5) AC15(1.5,-4.5) AC16(2,-4.5) AC17(2.5,-4.5) AC18(3,-4.5) AC19(3.5,-4.5) AC20(4,-4.5) AC21(4.5,-4.5) AC22(5,-4.5) AC23(5.5,-4.5) AD1(-5.5,-5) AD2(-5,-5) AD3(-4.5,-5) AD4(-4,-5) AD5(-3.5,-5) AD6(-3,-5) AD7(-2.5,-5) AD8(-2,-5) AD9(-1.5,-5) AD10(-1,-5) AD11(-0.5,-5) AD12(0,-5) AD13(0.5,-5) AD14(1,-5) AD15(1.5,-5) AD16(2,-5) AD17(2.5,-5) AD18(3,-5) AD19(3.5,-5) AD20(4,-5) AD21(4.5,-5) AD22(5,-5) AD23(5.5,-5) AE1(-5.5,-5.5) AE2(-5,-5.5) AE3(-4.5,-5.5) AE4(-4,-5.5) AE5(-3.5,-5.5) AE6(-3,-5.5) AE7(-2.5,-5.5) AE8(-2,-5.5) AE9(-1.5,-5.5) AE10(-1,-5.5) AE11(-0.5,-5.5) AE12(0,-5.5) AE13(0.5,-5.5) AE14(1,-5.5) AE15(1.5,-5.5) AE16(2,-5.5) AE17(2.5,-5.5) AE18(3,-5.5) AE19(3.5,-5.5) AE20(4,-5.5) AE21(4.5,-5.5) AE22(5,-5.5) AE23(5.5,-5.5) AF1(-5.5,-6) AF2(-5,-6) AF3(-4.5,-6) AF4(-4,-6) AF5(-3.5,-6) AF6(-3,-6) AF7(-2.5,-6) AF8(-2,-6) AF9(-1.5,-6) AF10(-1,-6) AF11(-0.5,-6) AF12(0,-6) AF13(0.5,-6) AF14(1,-6) AF15(1.5,-6) AF16(2,-6) AF17(2.5,-6) AF18(3,-6) AF19(3.5,-6) AF20(4,-6) AF21(4.5,-6) AF22(5,-6) AF23(5.5,-6) AG1(-5.5,-6.5) AG2(-5,-6.5) AG3(-4.5,-6.5) AG4(-4,-6.5) AG5(-3.5,-6.5) AG8(-2,-6.5) AG9(-1.5,-6.5) AG10(-1,-6.5) AG11(-0.5,-6.5) AG18(3,-6.5) AG19(3.5,-6.5) AG20(4,-6.5) AG21(4.5,-6.5) AG22(5,-6.5) AG23(5.5,-6.5) B1(-5.5,6) B2(-5,6) B3(-4.5,6) B4(-4,6) B5(-3.5,6) B6(-3,6) B7(-2.5,6) B8(-2,6) B9(-1.5,6) B10(-1,6) B11(-0.5,6) B12(0,6) B13(0.5,6) B14(1,6) B15(1.5,6) B16(2,6) B17(2.5,6) B18(3,6) B19(3.5,6) B20(4,6) B21(4.5,6) B22(5,6) B23(5.5,6) C1(-5.5,5.5) C2(-5,5.5) C3(-4.5,5.5) C4(-4,5.5) C5(-3.5,5.5) C6(-3,5.5) C7(-2.5,5.5) C8(-2,5.5) C9(-1.5,5.5) C10(-1,5.5) C11(-0.5,5.5) C12(0,5.5) C13(0.5,5.5) C14(1,5.5) C15(1.5,5.5) C16(2,5.5) C17(2.5,5.5) C18(3,5.5) C19(3.5,5.5) C20(4,5.5) C21(4.5,5.5) C22(5,5.5) C23(5.5,5.5) D1(-5.5,5) D2(-5,5) D3(-4.5,5) D4(-4,5) D5(-3.5,5) D6(-3,5) D7(-2.5,5) D8(-2,5) D9(-1.5,5) D10(-1,5) D11(-0.5,5) D12(0,5) D13(0.5,5) D14(1,5) D15(1.5,5) D16(2,5) D17(2.5,5) D18(3,5) D19(3.5,5) D20(4,5) D21(4.5,5) D22(5,5) D23(5.5,5) E1(-5.5,4.5) E2(-5,4.5) E3(-4.5,4.5) E4(-4,4.5) E5(-3.5,4.5) E6(-3,4.5) E7(-2.5,4.5) E8(-2,4.5) E9(-1.5,4.5) E10(-1,4.5) E11(-0.5,4.5) E12(0,4.5) E13(0.5,4.5) E14(1,4.5) E15(1.5,4.5) E16(2,4.5) E17(2.5,4.5) E18(3,4.5) E19(3.5,4.5) E20(4,4.5) E21(4.5,4.5) E22(5,4.5) E23(5.5,4.5) F1(-5.5,4) F2(-5,4) F3(-4.5,4) F4(-4,4) F5(-3.5,4) F6(-3,4) F7(-2.5,4) F8(-2,4) F9(-1.5,4) F10(-1,4) F11(-0.5,4) F12(0,4) F13(0.5,4) F14(1,4) F15(1.5,4) F16(2,4) F17(2.5,4) F18(3,4) F19(3.5,4) F20(4,4) F21(4.5,4) F22(5,4) F23(5.5,4) G1(-5.5,3.5) G2(-5,3.5) G3(-4.5,3.5) G4(-4,3.5) G5(-3.5,3.5) G6(-3,3.5) G7(-2.5,3.5) G8(-2,3.5) G9(-1.5,3.5) G10(-1,3.5) G11(-0.5,3.5) G12(0,3.5) G13(0.5,3.5) G14(1,3.5) G15(1.5,3.5) G16(2,3.5) G17(2.5,3.5) G18(3,3.5) G19(3.5,3.5) G20(4,3.5) G21(4.5,3.5) G22(5,3.5) G23(5.5,3.5) H1(-5.5,3) H2(-5,3) H3(-4.5,3) H4(-4,3) H5(-3.5,3) H6(-3,3) H7(-2.5,3) H8(-2,3) H9(-1.5,3) H10(-1,3) H11(-0.5,3) H12(0,3) H13(0.5,3) H14(1,3) H15(1.5,3) H16(2,3) H17(2.5,3) H18(3,3) H19(3.5,3) H20(4,3) H21(4.5,3) H22(5,3) H23(5.5,3) J1(-5.5,2.5) J2(-5,2.5) J3(-4.5,2.5) J4(-4,2.5) J5(-3.5,2.5) J6(-3,2.5) J7(-2.5,2.5) J8(-2,2.5) J9(-1.5,2.5) J10(-1,2.5) J11(-0.5,2.5) J12(0,2.5) J13(0.5,2.5) J14(1,2.5) J15(1.5,2.5) J16(2,2.5) J17(2.5,2.5) J18(3,2.5) J19(3.5,2.5) J20(4,2.5) J21(4.5,2.5) J22(5,2.5) J23(5.5,2.5) K1(-5.5,2) K2(-5,2) K3(-4.5,2) K4(-4,2) K5(-3.5,2) K6(-3,2) K7(-2.5,2) K8(-2,2) K9(-1.5,2) K10(-1,2) K11(-0.5,2) K12(0,2) K13(0.5,2) K14(1,2) K15(1.5,2) K16(2,2) K17(2.5,2) K18(3,2) K19(3.5,2) K20(4,2) K21(4.5,2) K22(5,2) K23(5.5,2) L1(-5.5,1.5) L2(-5,1.5) L3(-4.5,1.5) L4(-4,1.5) L5(-3.5,1.5) L6(-3,1.5) L7(-2.5,1.5) L8(-2,1.5) L9(-1.5,1.5) L10(-1,1.5) L11(-0.5,1.5) L12(0,1.5) L13(0.5,1.5) L14(1,1.5) L15(1.5,1.5) L16(2,1.5) L17(2.5,1.5) L18(3,1.5) L19(3.5,1.5) L20(4,1.5) L21(4.5,1.5) L22(5,1.5) L23(5.5,1.5) M1(-5.5,1) M2(-5,1) M3(-4.5,1) M4(-4,1) M5(-3.5,1) M6(-3,1) M7(-2.5,1) M8(-2,1) M9(-1.5,1) M10(-1,1) M11(-0.5,1) M12(0,1) M13(0.5,1) M14(1,1) M15(1.5,1) M16(2,1) M17(2.5,1) M18(3,1) M19(3.5,1) M20(4,1) M21(4.5,1) M22(5,1) M23(5.5,1) N1(-5.5,0.5) N2(-5,0.5) N3(-4.5,0.5) N4(-4,0.5) N5(-3.5,0.5) N6(-3,0.5) N7(-2.5,0.5) N8(-2,0.5) N9(-1.5,0.5) N10(-1,0.5) N11(-0.5,0.5) N12(0,0.5) N13(0.5,0.5) N14(1,0.5) N15(1.5,0.5) N16(2,0.5) N17(2.5,0.5) N18(3,0.5) N19(3.5,0.5) N20(4,0.5) N21(4.5,0.5) N22(5,0.5) N23(5.5,0.5) P1(-5.5,0) P2(-5,0) P3(-4.5,0) P4(-4,0) P5(-3.5,0) P6(-3,0) P7(-2.5,0) P8(-2,0) P9(-1.5,0) P10(-1,0) P11(-0.5,0) P12(0,0) P13(0.5,0) P14(1,0) P15(1.5,0) P16(2,0) P17(2.5,0) P18(3,0) P19(3.5,0) P20(4,0) P21(4.5,0) P22(5,0) P23(5.5,0) R1(-5.5,-0.5) R2(-5,-0.5) R3(-4.5,-0.5) R4(-4,-0.5) R5(-3.5,-0.5) R6(-3,-0.5) R7(-2.5,-0.5) R8(-2,-0.5) R9(-1.5,-0.5) R10(-1,-0.5) R11(-0.5,-0.5) R12(0,-0.5) R13(0.5,-0.5) R14(1,-0.5) R15(1.5,-0.5) R16(2,-0.5) R17(2.5,-0.5) R18(3,-0.5) R19(3.5,-0.5) R20(4,-0.5) R21(4.5,-0.5) R22(5,-0.5) R23(5.5,-0.5) T1(-5.5,-1) T2(-5,-1) T3(-4.5,-1) T4(-4,-1) T5(-3.5,-1) T6(-3,-1) T7(-2.5,-1) T8(-2,-1) T9(-1.5,-1) T10(-1,-1) T11(-0.5,-1) T12(0,-1) T13(0.5,-1) T14(1,-1) T15(1.5,-1) T16(2,-1) T17(2.5,-1) T18(3,-1) T19(3.5,-1) T20(4,-1) T21(4.5,-1) T22(5,-1) T23(5.5,-1) U1(-5.5,-1.5) U2(-5,-1.5) U3(-4.5,-1.5) U4(-4,-1.5) U5(-3.5,-1.5) U6(-3,-1.5) U7(-2.5,-1.5) U8(-2,-1.5) U9(-1.5,-1.5) U10(-1,-1.5) U11(-0.5,-1.5) U12(0,-1.5) U13(0.5,-1.5) U14(1,-1.5) U15(1.5,-1.5) U16(2,-1.5) U17(2.5,-1.5) U18(3,-1.5) U19(3.5,-1.5) U20(4,-1.5) U21(4.5,-1.5) U22(5,-1.5) U23(5.5,-1.5) V1(-5.5,-2) V2(-5,-2) V3(-4.5,-2) V4(-4,-2) V5(-3.5,-2) V6(-3,-2) V7(-2.5,-2) V8(-2,-2) V9(-1.5,-2) V10(-1,-2) V11(-0.5,-2) V12(0,-2) V13(0.5,-2) V14(1,-2) V15(1.5,-2) V16(2,-2) V17(2.5,-2) V18(3,-2) V19(3.5,-2) V20(4,-2) V21(4.5,-2) V22(5,-2) V23(5.5,-2) W1(-5.5,-2.5) W2(-5,-2.5) W3(-4.5,-2.5) W4(-4,-2.5) W5(-3.5,-2.5) W6(-3,-2.5) W7(-2.5,-2.5) W8(-2,-2.5) W9(-1.5,-2.5) W10(-1,-2.5) W11(-0.5,-2.5) W12(0,-2.5) W13(0.5,-2.5) W14(1,-2.5) W15(1.5,-2.5) W16(2,-2.5) W17(2.5,-2.5) W18(3,-2.5) W19(3.5,-2.5) W20(4,-2.5) W21(4.5,-2.5) W22(5,-2.5) W23(5.5,-2.5) Y1(-5.5,-3) Y2(-5,-3) Y3(-4.5,-3) Y4(-4,-3) Y5(-3.5,-3) Y6(-3,-3) Y7(-2.5,-3) Y8(-2,-3) Y9(-1.5,-3) Y10(-1,-3) Y11(-0.5,-3) Y12(0,-3) Y13(0.5,-3) Y14(1,-3) Y15(1.5,-3) Y16(2,-3) Y17(2.5,-3) Y18(3,-3) Y19(3.5,-3) Y20(4,-3) Y21(4.5,-3) Y22(5,-3) Y23(5.5,-3)
  round 0.25 smd: A8(-2,6.5) A9(-1.5,6.5) A10(-1,6.5) A11(-0.5,6.5) A17(2.5,6.5) A18(3,6.5) AG6(-3,-6.5) AG7(-2.5,-6.5) AG12(0,-6.5) AG13(0.5,-6.5) AG14(1,-6.5) AG15(1.5,-6.5) AG16(2,-6.5) AG17(2.5,-6.5)
HDR_1X4_50MIL_WIRE_P1R1
  round 0.8 smd: 1(0,-1.1) 2(0,0) 3(0,1.1) 4(0,2.2)
L110NH_XGL4020_4X4X2R1
  rect 1x3.4 smd: 1(-1.185,0) 2(1.185,0)
M95P32_WLCSP8
  round 0.27 smd: A1(0.4,1.05) A2(-0.4,1.05) B1(0.4,0.35) B2(-0.4,0.35) C1(0.4,-0.35) C2(-0.4,-0.35) D1(0.4,-1.05) D2(-0.4,-1.05)
OSFP_1600G_FINGER
  rect 2.35x0.38 smd: 1(0.15,-0.3) 4(0.15,-2.1) 7(0.15,-3.9) 10(0.15,-5.7) 13(0.15,-7.5) 18(0.15,-10.5) 21(0.15,-12.3) 24(0.15,-14.1) 27(0.15,-15.9) 30(0.15,-17.7) 31(0.15,-17.4) 34(0.15,-15.6) 37(0.15,-13.8) 40(0.15,-12) 43(0.15,-10.2) 48(0.15,-7.2) 51(0.15,-5.4) 54(0.15,-3.6) 57(0.15,-1.8) 60(0.15,0)
  rect 1.5x0.38 smd: 2(-0.275,-0.9) 3(-0.275,-1.5) 5(-0.275,-2.7) 6(-0.275,-3.3) 8(-0.275,-4.5) 9(-0.275,-5.1) 11(-0.275,-6.3) 12(-0.275,-6.9) 14(-0.275,-8.1) 17(-0.275,-9.9) 19(-0.275,-11.1) 20(-0.275,-11.7) 22(-0.275,-12.9) 23(-0.275,-13.5) 25(-0.275,-14.7) 26(-0.275,-15.3) 28(-0.275,-16.5) 29(-0.275,-17.1) 32(-0.275,-16.8) 33(-0.275,-16.2) 35(-0.275,-15) 36(-0.275,-14.4) 38(-0.275,-13.2) 39(-0.275,-12.6) 41(-0.275,-11.4) 42(-0.275,-10.8) 44(-0.275,-9.6) 47(-0.275,-7.8) 49(-0.275,-6.6) 50(-0.275,-6) 52(-0.275,-4.8) 53(-0.275,-4.2) 55(-0.275,-3) 56(-0.275,-2.4) 58(-0.275,-1.2) 59(-0.275,-0.6)
  rect 2.05x0.98 smd: 15_16(-0.001,-9) 45_46(-0.001,-8.701)
SG2016EGN
  rect 0.525x0.75 smd: 1(-0.805,-0.625) 3(0.805,-0.625) 4(0.805,0.625) 6(-0.805,0.625)
  rect 0.575x0.75 smd: 2(0,-0.625) 5(0,0.625)
TDFN_MIC842
  rect 0.25x0.5 smd: 1(-0.25,-0.7) 2(0.25,-0.7) 3(0.25,0.7) 4(-0.25,0.7)
  rect 0.86x0.5 smd: 5(0,0)
TP80
  round 0.6 smd: 1(0,0)
TPS62864_DSBGA
  round 0.2 smd: A1(-0.35,0.7) A2(0,0.7) A3(0.35,0.7) B1(-0.35,0.35) B2(0,0.35) B3(0.35,0.35) C1(-0.35,0) C2(0,0) C3(0.35,0) D1(-0.35,-0.35) D2(0,-0.35) D3(0.35,-0.35) E1(-0.35,-0.7) E2(0,-0.7) E3(0.35,-0.7)
VQFN
  custom 0.15x0.15 smd: 1(-1.425,1.925) 8(-1.425,-1.925) 13(1.425,-1.925) 20(1.425,1.925)
  rect 0.6x0.25 smd: 2(-1.425,1.25) 3(-1.425,0.75) 4(-1.425,0.25) 5(-1.425,-0.25) 6(-1.425,-0.75) 7(-1.425,-1.25) 14(1.425,-1.25) 15(1.425,-0.75) 16(1.425,-0.25) 17(1.425,0.25) 18(1.425,0.75) 19(1.425,1.25)
  rect 0.25x0.6 smd: 9(-0.75,-1.925) 10(-0.25,-1.925) 11(0.25,-1.925) 12(0.75,-1.925) 21(0.75,1.925) 22(0.25,1.925) 23(-0.25,1.925) 24(-0.75,1.925)
  rect 0.75x1.25 smd: 25(-0.5,0.75) 27(0.5,0.75)
  rect 1.75x1.25 smd: 26(0,-0.75)
WLCSP4
  round 0.2 smd: A1(-0.175,0.175) A2(0.175,0.175) B1(-0.175,-0.175) B2(0.175,-0.175)
WLCSP80
  round 0.22 smd: A1(-1.364,1.326) A3(-0.758,1.326) A5(-0.152,1.326) A7(0.455,1.326) A9(1.061,1.326) B2(-1.061,1.151) B4(-0.455,1.151) B6(0.151,1.151) B8(0.758,1.151) B10(1.364,1.151) C1(-1.364,0.976) C3(-0.758,0.976) C5(-0.152,0.976) C7(0.455,0.976) C9(1.061,0.976) D2(-1.061,0.801) D4(-0.455,0.801) D6(0.151,0.801) D8(0.758,0.801) D10(1.364,0.801) E1(-1.364,0.626) E3(-0.758,0.626) E5(-0.152,0.626) E7(0.455,0.626) E9(1.061,0.626) F2(-1.061,0.451) F4(-0.455,0.451) F6(0.151,0.451) F8(0.758,0.451) F10(1.364,0.451) G1(-1.364,0.276) G3(-0.758,0.276) G5(-0.152,0.276) G7(0.455,0.276) G9(1.061,0.276) H2(-1.061,0.101) H4(-0.455,0.101) H6(0.151,0.101) H8(0.758,0.101) H10(1.364,0.101) J1(-1.364,-0.074) J3(-0.758,-0.074) J5(-0.152,-0.074) J7(0.455,-0.074) J9(1.061,-0.074) K2(-1.061,-0.249) K4(-0.455,-0.249) K6(0.151,-0.249) K8(0.758,-0.249) K10(1.364,-0.249) L1(-1.364,-0.424) L3(-0.758,-0.424) L5(-0.152,-0.424) L7(0.455,-0.424) L9(1.061,-0.424) M2(-1.061,-0.599) M4(-0.455,-0.599) M6(0.151,-0.599) M8(0.758,-0.599) M10(1.364,-0.599) N1(-1.364,-0.774) N3(-0.758,-0.774) N5(-0.152,-0.774) N7(0.455,-0.774) N9(1.061,-0.774) P2(-1.061,-0.949) P4(-0.455,-0.949) P6(0.151,-0.949) P8(0.758,-0.949) P10(1.364,-0.949) R1(-1.364,-1.124) R3(-0.758,-1.124) R5(-0.152,-1.124) R7(0.455,-1.124) R9(1.061,-1.124) T2(-1.061,-1.299) T4(-0.455,-1.299) T6(0.151,-1.299) T8(0.758,-1.299) T10(1.364,-1.299)
WQFN-10
  rect 0.58x0.25 smd: 1(-0.66,0.75) 4(-0.66,-0.75) 6(0.66,-0.75) 9(0.66,0.75)
  rect 0.83x0.25 smd: 2(-0.535,0.25) 3(-0.535,-0.25) 7(0.535,-0.25) 8(0.535,0.25)
  rect 0.25x0.58 smd: 5(0,-0.91) 10(0,0.91)
X1-DFN1006-2
  rect 0.4x0.7 smd: 1(-0.35,0) 2(0.35,0)
X2SON8
  custom 0.05x0.05 smd: 1(-0.39,0.5) 2(-0.39,0) 3(-0.39,-0.5) 5(0.39,-0.5) 6(0.39,0) 7(0.39,0.5)
  rect 0.22x0.22 smd rot 135: 4(0,-0.27) 8(0,0.27)
X2SON12
  custom 0.05x0.05 smd: 1(-0.515,0.69) 5(-0.515,-0.69) 7(0.515,-0.69) 11(0.515,0.69)
  custom 0.05x0.05 smd rot 135: 2(-0.22,0.37) 8(0.22,-0.37)
  custom 0.065x0.065 smd: 3(-0.5,0) 6(0,-0.85) 9(0.5,0) 12(0,0.85)
  custom 0.05x0.05 smd rot 45: 4(-0.22,-0.37) 10(0.22,0.37)

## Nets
3V3_IN_DDM: R600.1 R601.1 U2.L7
AVDDH_1P2: C795.1 C796.1 C797.1 C798.1 C837.1 C838.1 C839.1 C840.1 C841.1 C842.1 C843.1 C844.1 C845.1 C846.1 C871.1 C872.1 C873.1 C874.1 C875.1 C876.1 C877.1 C878.1 C898.1 C899.1 L14.1 U1.AA16 U1.AA17 U1.AB16 U1.AB17 U1.F16 U1.F17 U1.G16 U1.G17 U1.H9 U1.H10 U1.J9 U1.J10 U1.W9 U1.W10 U1.Y9 U1.Y10
AVDDLPLL_0P94: C79.1 C566.1 C778.1 C779.1 C780.1 C785.1 C786.1 C817.1 C818.1 C819.1 C820.1 C865.1 C866.1 C938.1 L9.1 U1.AC5 U1.AC6 U1.AC9 U1.AC10 U1.AD9 U1.AD10 U1.D9 U1.D10 U1.E5 U1.E6 U1.E9 U1.E10 U1.M9 U1.M10 U1.N9 U1.N10 U1.R9 U1.R10 U1.T9 U1.T10
AVDDLPLLLINE_0P94: C346.1 C781.1 C782.1 C783.1 C784.1 C787.1 C788.1 C821.1 C822.1 C823.1 C824.1 C825.1 C826.1 C827.1 C828.1 L19.1 U1.AC18 U1.AC19 U1.AD18 U1.AD19 U1.D18 U1.D19 U1.E18 U1.E19 U1.M18 U1.M19 U1.N18 U1.N19 U1.R18 U1.R19 U1.T18 U1.T19
AVDDLTXRX_0P94: C799.1 C801.1 C802.1 C803.1 C805.1 C806.1 C847.1 C848.1 C849.1 C850.1 C851.1 C852.1 C853.1 C854.1 C855.1 C856.1 C881.1 C882.1 C883.1 C884.1 C885.1 C886.1 C887.1 C888.1 C889.1 C890.1 C936.1 C937.1 L96.2 U1.AA7 U1.AA8 U1.AB7 U1.AB8 U1.F7 U1.F8 U1.G7 U1.G8 U1.H5 U1.H6 U1.J5 U1.J6 U1.K7 U1.K8 U1.K16 U1.K17 U1.L7 U1.L8 U1.L16 U1.L17 U1.M5 U1.M6 U1.N5 U1.N6 U1.R5 U1.R6 U1.T5 U1.T6 U1.U7 U1.U8 U1.U16 U1.U17 U1.V7 U1.V8 U1.V16 U1.V17 U1.W5 U1.W6 U1.Y5 U1.Y6
AVDDTXDRV_0P94: C789.1 C790.1 C791.1 C792.1 C793.1 C794.1 C829.1 C830.1 C831.1 C832.1 C833.1 C834.1 C835.1 C836.1 L30.1 U1.H18 U1.H19 U1.J18 U1.J19 U1.W18 U1.W19 U1.Y18 U1.Y19
GND: C40.1 C42.1 C43.1 C45.2 C48.2 C49.2 C54.2 C56.2 C60.1 C62.2 C67.2 C72.2 C78.2 C81.2 C82.1 C83.1 C169.1 C170.1 C172.1 C173.1 C174.1 C266.2 C338.2 C342.2 C417.2 C419.1 C420.2 C421.2 C424.2 C425.1 C426.2 C427.2 C428.2 C431.2 C437.2 C441.2 C444.2 C445.2 C447.2 C454.2 C455.1 C456.2 C458.2 C459.2 C460.2 C461.2 C466.2 C467.2 C468.2 C469.2 C475.1 C476.1 C477.1 C478.1 C479.1 C480.1 C481.1 C485.2 C492.2 C493.2 C494.2 C497.2 C498.2 C499.2 C500.2 C501.2 C502.2 C503.2 C504.2 C508.2 C566.2 C642.2 C643.2 C644.2 C645.2 C646.2 C648.2 C649.2 C652.2 C653.2 C654.2 C655.2 C656.2 C657.2 C658.2 C659.2 C661.2 C664.2 C665.2 C744.2 C745.2 C746.2 C747.2 C748.2 C749.2 C750.2 C751.2 C752.2 C753.2 C754.2 C755.2 C756.2 C757.2 C758.2 C759.2 C760.2 C761.2 C762.2 C763.2 C764.2 C765.2 C766.2 C767.2 C778.2 C779.2 C780.2 C781.2 C782.2 C783.2 C784.2 C785.2 C786.2 C787.2 C788.2 C789.2 C790.2 C791.2 C792.2 C793.2 C794.2 C795.2 C796.2 C797.2 C798.2 C799.2 C801.2 C802.2 C803.2 C805.2 C806.2 C807.2 C808.2 C809.2 C810.2 C811.2 C812.2 C813.2 C814.2 C815.2 C816.2 C817.2 C818.2 C819.2 C820.2 C821.2 C822.2 C823.2 C824.2 C825.2 C826.2 C827.2 C828.2 C829.2 C830.2 C831.2 C832.2 C833.2 C834.2 C835.2 C836.2 C837.2 C838.2 C839.2 C840.2 C841.2 C842.2 C843.2 C844.2 C845.2 C846.2 C847.2 C848.2 C849.2 C850.2 C851.2 C852.2 C853.2 C854.2 C855.2 C856.2 C857.2 C858.2 C859.2 C860.2 C861.2 C862.2 C863.2 C864.2 C865.2 C866.2 C871.2 C872.2 C873.2 C874.2 C875.2 C876.2 C877.2 C878.2 C880.2 C881.2 C882.2 C883.2 C884.2 C885.2 C886.2 C887.2 C888.2 C889.2 C890.2 C891.1 C892.1 C898.2 C899.2 C909.2 C910.1 C914.2 C915.2 C932.1 C933.1 C934.2 C935.2 C936.2 C937.2 C938.2 C940.2 C941.2 C942.2 C943.2 C944.2 C945.2 D1.2 J1.1 J1.4 J1.7 J1.10 J1.13 J1.18 J1.21 J1.24 J1.27 J1.30 J1.31 J1.34 J1.37 J1.40 J1.43 J1.48 J1.51 J1.54 J1.57 J1.60 J2.1 J2.4 J3.1 J3.4 J4.1 J4.4 J5.1 J5.4 J6.1 J6.4 J7.1 J7.4 J8.1 J8.4 J9.1 J9.4 J10.1 J10.4 J11.1 J11.4 J12.1 J12.4 J13.1 J13.4 J14.1 J14.4 J15.1 J15.4 J16.1 J16.4 J17.1 J17.4 J18.1 R6.1 R24.2 R25.2 R35.2 R36.2 R41.2 R44.2 R46.1 R63.1 R73.2 R79.2 R404.2 R411.2 R581.2 R582.2 R601.2 R602.2 R610.1 R623.1 R635.2 R649.2 R650.2 R685.2 R711.1 R715.2 R718.2 R719.2 R735.1 R755.2 R756.2 R759.2 R760.2 R761.1 R762.1 R764.2 R765.2 R766.2 R767.2 R770.2 R815.2 R833.2 R834.2 R835.2 R836.2 R837.2 R838.2 R839.2 R840.2 R842.2 R843.2 R849.2 R850.2 U1.A1 U1.A2 U1.A3 U1.A4 U1.A7 U1.A10 U1.A16 U1.A19 U1.A22 U1.A23 U1.AA2 U1.AA4 U1.AA5 U1.AA6 U1.AA9 U1.AA10 U1.AA14 U1.AA15 U1.AA18 U1.AA19 U1.AA20 U1.AA22 U1.AB2 U1.AB4 U1.AB5 U1.AB6 U1.AB9 U1.AB10 U1.AB14 U1.AB15 U1.AB18 U1.AB19 U1.AB20 U1.AB22 U1.AC1 U1.AC2 U1.AC3 U1.AC4 U1.AC7 U1.AC8 U1.AC11 U1.AC12 U1.AC13 U1.AC16 U1.AC17 U1.AC20 U1.AC21 U1.AC22 U1.AC23 U1.AD2 U1.AD4 U1.AD8 U1.AD11 U1.AD16 U1.AD17 U1.AD20 U1.AD22 U1.AE2 U1.AE4 U1.AE8 U1.AE17 U1.AE20 U1.AE22 U1.AF1 U1.AF2 U1.AF3 U1.AF4 U1.AF5 U1.AF6 U1.AF10 U1.AF13 U1.AF14 U1.AF19 U1.AF20 U1.AF21 U1.AF22 U1.AF23 U1.AG1 U1.AG2 U1.AG3 U1.AG6 U1.AG13 U1.AG14 U1.AG19 U1.AG22 U1.AG23(\VSS_318\) U1.B2 U1.B4 U1.B5 U1.B6 U1.B7 U1.B19 U1.B20 U1.B21 U1.B22 U1.B23 U1.C2 U1.C4 U1.C14 U1.C17 U1.C20 U1.C22 U1.D1 U1.D2 U1.D3 U1.D4 U1.D8 U1.D11 U1.D16 U1.D17 U1.D20 U1.D22 U1.E2 U1.E4 U1.E7 U1.E8 U1.E11 U1.E12 U1.E13 U1.E16 U1.E17 U1.E20 U1.E21 U1.E22 U1.E23 U1.F2 U1.F4 U1.F5 U1.F6 U1.F9 U1.F10 U1.F14 U1.F15 U1.F18 U1.F19 U1.F20 U1.F22 U1.G1 U1.G2 U1.G3 U1.G4 U1.G5 U1.G6 U1.G9 U1.G10 U1.G14 U1.G15 U1.G18 U1.G19 U1.G20 U1.G22 U1.H2 U1.H4 U1.H7 U1.H8 U1.H11 U1.H12 U1.H13 U1.H16 U1.H17 U1.H20 U1.H21 U1.H22 U1.H23 U1.J2 U1.J4 U1.J7 U1.J8 U1.J11 U1.J12 U1.J13 U1.J16 U1.J17 U1.J20 U1.J22 U1.K1 U1.K2 U1.K3 U1.K4 U1.K5 U1.K6 U1.K9 U1.K10 U1.K14 U1.K15 U1.K18 U1.K19 U1.K20 U1.K22 U1.L2 U1.L4 U1.L5 U1.L6 U1.L9 U1.L10 U1.L14 U1.L15 U1.L18 U1.L19 U1.L20 U1.L21 U1.L22 U1.L23 U1.M2 U1.M4 U1.M7 U1.M8 U1.M11 U1.M12 U1.M13 U1.M16 U1.M17 U1.M20 U1.M22 U1.N1 U1.N2 U1.N3 U1.N4 U1.N7 U1.N8 U1.N11 U1.N12 U1.N13 U1.N16 U1.N17 U1.N20 U1.N22 U1.P1 U1.P2 U1.P3 U1.P4 U1.P5 U1.P6 U1.P7 U1.P8 U1.P9 U1.P10 U1.P14 U1.P15 U1.P17 U1.P18 U1.P19 U1.P20 U1.P21 U1.P22 U1.P23 U1.R2 U1.R4 U1.R7 U1.R8 U1.R11 U1.R12 U1.R13 U1.R16 U1.R17 U1.R20 U1.R22 U1.T2 U1.T4 U1.T7 U1.T8 U1.T11 U1.T12 U1.T13 U1.T16 U1.T17 U1.T20 U1.T22 U1.U1 U1.U2 U1.U3 U1.U4 U1.U5 U1.U6 U1.U9 U1.U10 U1.U14 U1.U15 U1.U18 U1.U19 U1.U20 U1.U21 U1.U22 U1.U23 U1.V2 U1.V4 U1.V5 U1.V6 U1.V9 U1.V10 U1.V14 U1.V15 U1.V18 U1.V19 U1.V20 U1.V22 U1.W2 U1.W4 U1.W7 U1.W8 U1.W11 U1.W12 U1.W13 U1.W16 U1.W17 U1.W20 U1.W22 U1.Y1 U1.Y2 U1.Y3 U1.Y4 U1.Y7 U1.Y8 U1.Y11 U1.Y12 U1.Y13 U1.Y16 U1.Y17 U1.Y20 U1.Y21 U1.Y22 U1.Y23 U2.B8 U2.D2 U2.G9 U2.H2 U2.N3(\VSSSMPS\) U2.N9 U2.P2 U2.P8 U4.2 U4.5 U8.B2 U10.4 U17.6 U20.7 U20.8 U20.13 U20.14 U20.22 U20.24 U20.25 U20.26 U20.27 U21.1 U21.4(\VSEL\) U21.7 U21.8 U21.13 U21.14 U21.19 U21.20 U21.22 U21.24 U21.25 U21.26 U21.27 U22.D2 U24.2 U24.5 U26.7 U26.8 U26.13 U26.14 U26.22 U26.24 U26.25 U26.26 U26.27 U32.5 U37.A1 U37.B1 U37.B2 U37.B3 U38.6 U46.6 U47.B1 U48.4 UNK647.2 Y1.3 Y2.3
VCC_3V3: C45.1 C82.2 C172.2 C338.1 C417.1 C420.1 C424.1 C427.1 C909.1 C914.1 D1.1(\K\) J18.4 L81.2 L82.1 L84.2 L85.1 L86.1 L91.1 L93.1 L95.2 R4.1 R13.1 R23.2 R28.1 R29.1 R32.2 R40.2 R62.1 R64.1 R233.2 R579.1 R580.1 R603.1 R622.1 R657.1 R857.2 U4.4(\VDD\) U8.A1 U10.2 U17.11(\VCCB\) U22.A1 U24.4(\VDD\) U32.6 U32.7 U32.8(\VOUT3\) U38.1 U38.12 U46.1 U46.12 U48.2
VCC_3V3_DMM: R23.1 R24.1 U2.P6
VCC_OSFP: C939.2 J1.15_16 J1.45_46(\VCC#45_46\) R600.2 U32.1 U32.2 U32.3 U32.4 U32.10
VDD_0P6: C56.1 C62.1 C72.1 C266.1 C431.1 C437.1 C441.1 C444.1 C445.1 C447.1 C454.1 C456.1 C466.1 C658.1 C659.1 C664.1 C665.1 C744.1 C745.1 C746.1 C747.1 C748.1 C749.1 C750.1 C751.1 C752.1 C753.1 C754.1 C755.1 C756.1 C757.1 C758.1 C759.1 C760.1 C761.1 C762.1 C763.1 C764.1 C765.1 C766.1 C767.1 C880.1 C934.1 C935.1 C942.1 C943.1 C944.1 C945.1 L4.2 L87.2 U1.AA11 U1.AA12 U1.AA13 U1.AB11 U1.AB12 U1.AB13 U1.AC14 U1.AC15 U1.AD14 U1.AD15 U1.D14 U1.D15 U1.E14 U1.E15 U1.F11 U1.F12 U1.F13 U1.G11 U1.G12 U1.G13 U1.H14 U1.H15 U1.J14 U1.J15 U1.K11 U1.K12 U1.K13 U1.L11 U1.L12 U1.L13 U1.M14 U1.M15 U1.N14 U1.N15 U1.R14 U1.R15 U1.T14 U1.T15 U1.U11 U1.U12 U1.U13 U1.V11 U1.V12 U1.V13 U1.W14 U1.W15 U1.Y14 U1.Y15 U2.M8 U20.1
VDD_0P6_EN: R607.1 R635.1 U2.G5
VDD_0P6_PG: R620.2 U20.21 U21.21
VDD_0P94: C493.1 C494.1 C502.1 C503.1 C504.1 C508.1 C661.1 L9.2 L19.2 L30.2 L88.2 L96.1 L98.1 U2.T10 U26.1
VDD_0P94_EN: R710.1 R715.1 U2.E1
VDD_0P94_PG: R621.2 U26.21
VDD_1P2: C642.1 C643.1 C644.1 C645.1 L14.2 L89.2 U2.J7 U37.A3
VDD_1P2_EN: R850.1 R852.1 U2.C1
VDD_1P2_PG: R756.1 U37.A2(\VSET/P\\G\\\)
VDD_1P8: C83.2 C421.1 C425.2 C426.1 C807.1 C808.1 C809.1 C810.1 C857.1 C858.1 C859.1 C860.1 C910.2 C915.1 C932.2 R22.1 R30.2 R75.2 R583.1 R640.1 R690.2 R691.2 R693.2 R694.2 R769.1 R771.2 R818.1 R819.1 R841.2 R854.2 R855.1 R856.1 U1.AD12 U1.AD13 U1.D12 U1.D13 U8.A2(\OUT\) U10.6(\VCCB\) U17.1 U38.11(\VCCB\) U46.11(\VCCB\) U47.A2 U48.6(\VCCB\)
VDD_3P3: C653.1 C654.1 C811.1 C812.1 C813.1 C814.1 C861.1 C862.1 L82.2 R780.1 R781.1 U1.AD5 U1.AD6 U1.D5 U1.D6
VDD_3P3_ESD0: C815.1 C863.1 R780.2 U1.D7
VDD_3P3_ESD1: C816.1 C864.1 R781.2 U1.AD7
VDDA: C475.2 C481.2 R640.2 U2.P10
VDDEFUSE_0P94: C940.1 C941.1 L98.2 U1.P11 U1.P16
VDDIO_1P8_EN: R602.1 U2.D6 U8.B1
VIN1: C54.1 C67.1 C428.1 C467.1 C468.1 C655.1 L85.2 R618.1 R620.1 R629.1 U20.5 U20.6 U20.15 U20.16 U20.18
VIN2: C485.1 C497.1 C498.1 C499.1 C500.1 C657.1 L86.2 R621.1 R748.1 R779.1 U26.5 U26.6 U26.15 U26.16 U26.18
VIN3: C646.1 C648.1 L93.2 U37.D1 U37.D2 U37.D3 UNK647.1
VIN4: C458.1 C459.1 C460.1 C461.1 C469.1 C656.1 L91.2 R778.1 U21.5 U21.6 U21.15 U21.16
BOOT0: R13.2 R63.2 U2.D8
CABLE_END_DETECT: R622.2 R623.2 U2.J5
COMP1: C81.1 R608.1 U20.23 U21.23
DEBUG_I2C_EN: R840.1 U2.J3 U48.8
DSP_CLK_EN: R44.1 R79.1 U2.R7 Y1.1 Y2.1
DSP_I2C_SCL_18: R818.2 U1.A12 U10.7 U48.7
DSP_I2C_SDA_18: R819.2 U1.AG9 U1.B13 U10.5 U48.5
DSP_PGOOD_M: R105.2 U2.K4
DSP_REFCLK0_N: C50.2 U1.A20
DSP_REFCLK0_P: C51.2 U1.A21
DSP_REFCLK1_N: C651.2 U1.AG20
DSP_REFCLK1_P: C650.2 U1.AG21
EEPROM_MISO: R30.1 U1.AG12 U17.5
EEPROM_MOSI: U1.C15 U17.3
EEPROM_SCK: U1.B18 U17.2
EEPROM_SS_N: U1.B16 U17.4
EEPROM_WP_N: R857.1 U2.K8 U22.C2(\W\\-DQ2\)
EN1: R607.2 R845.1 U20.2
HRXN1: C200.1 U1.AD1
HRXN2: C202.1 U1.AD3
HRXN3: C204.1 U1.AA1
HRXN4: C206.1 U1.AA3
HRXN5: C208.1 U1.V1
HRXN6: C210.1 U1.V3
HRXN7: C212.1 U1.R1
HRXN8: C214.1 U1.R3
HRXP1: C199.1 U1.AE1
HRXP2: C201.1 U1.AE3
HRXP3: C203.1 U1.AB1
HRXP4: C205.1 U1.AB3
HRXP5: C207.1 U1.W1
HRXP6: C209.1 U1.W3
HRXP7: C211.1 U1.T1
HRXP8: C213.1 U1.T3
HTXN1: C216.2 U1.C3
HTXN2: C218.2 U1.C1
HTXN3: C220.2 U1.F3
HTXN4: C222.2 U1.F1
HTXN5: C224.2 U1.J3
HTXN6: C226.2 U1.J1
HTXN7: C228.2 U1.M3
HTXN8: C230.2 U1.M1
HTXP1: C215.2 U1.B3
HTXP2: C217.2 U1.B1
HTXP3: C219.2 U1.E3
HTXP4: C221.2 U1.E1
HTXP5: C223.2 U1.H3
HTXP6: C225.2 U1.H1
HTXP7: C227.2 U1.L3
HTXP8: C229.2 U1.L1
INT/RSTN: J1.44 R3.2 R31.1 R657.2 U4.3
LOL_1N: U1.C16 U2.K2
LOL_2N: U1.AG8 U2.H8
LOL_3N: U1.AF17 U2.H4
LOL_4N: U1.AG17 U2.N7
LOL_5N: U1.AG7 U2.L9
LOL_6N: U1.AF18 U2.L5
LOL_7N: U1.AG18 U2.M6
LOL_8N: U1.AE11 U2.G7
LPWN/PRSN: J1.17 R5.1 R843.1 U24.3
LRXN1: J4.3 U1.AD21
LRXN2: J8.3 U1.AA21
LRXN3: J12.3 U1.V21
LRXN4: J16.3 U1.R21
LRXN5: J5.3 U1.M21
LRXN6: J9.3 U1.J21
LRXN7: J13.3 U1.F21
LRXN8: J17.3 U1.C21
LRXP1: J4.2 U1.AE21
LRXP2: J8.2 U1.AB21
LRXP3: J12.2 U1.W21
LRXP4: J16.2 U1.T21
LRXP5: J5.2 U1.N21
LRXP6: J9.2 U1.K21
LRXP7: J13.2 U1.G21
LRXP8: J17.2 U1.D21
LTX_N1: C917.1 U1.AD23
LTX_N2: C919.1 U1.AA23
LTX_N3: C921.1 U1.V23
LTX_N4: C923.1 U1.R23
LTX_N5: C925.1 U1.M23
LTX_N6: C927.1 U1.J23
LTX_N7: C929.1 U1.F23
LTX_N8: C931.1 U1.C23
LTX_P1: C916.1 U1.AE23
LTX_P2: C918.1 U1.AB23
LTX_P3: C920.1 U1.W23
